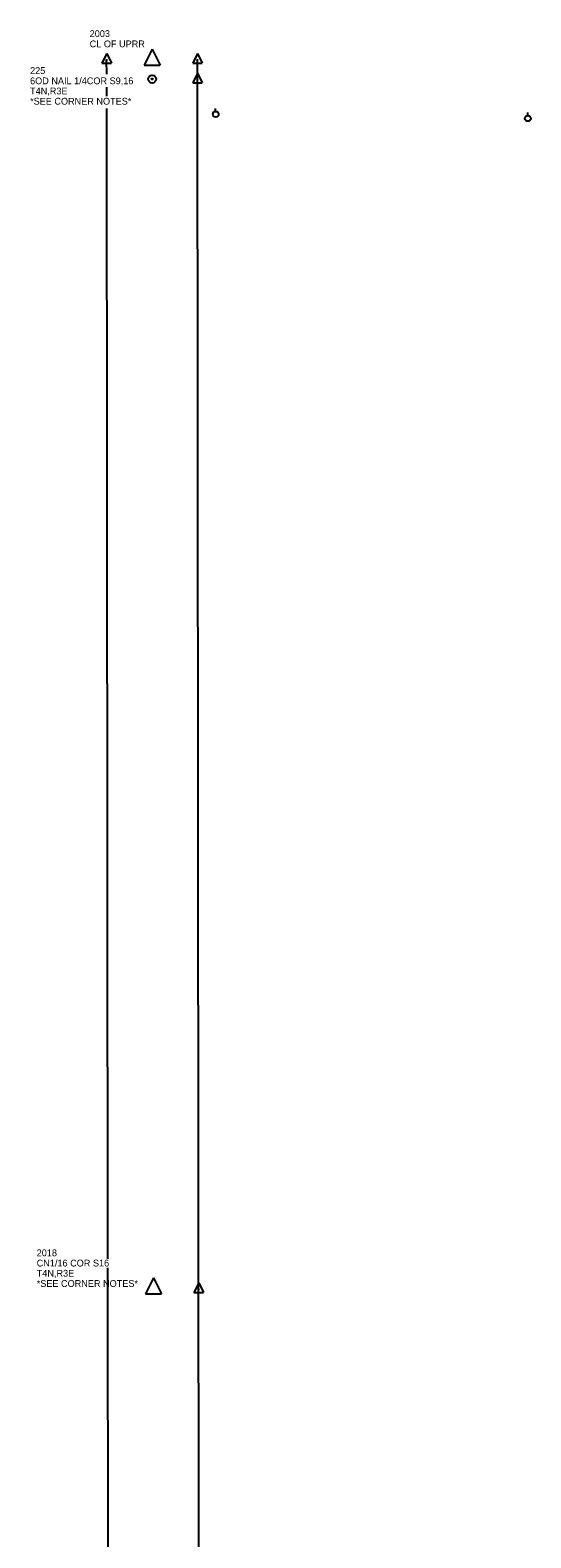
# Model space of a CAD drawing. Extents: x 1674300 to 1677920, y 225056 to 231852.
# Drawn here: x 1674554 to 1675105, y 230191 to 231852 of the extents above; entities that cross this region are included whole.
import ezdxf

# ---------------------------------------------------------------- set-up
doc = ezdxf.new("R2010")
doc.units = 0
for name, color, linetype in [('S_CAL_CORNER', 7, 'Continuous'), ('S_CAL_CORNER_ANNOT', 7, 'Continuous'), ('S_EXIST_ROW', 7, 'Continuous'), ('S_IRON_PIN', 7, 'Continuous'), ('S_IRON_PIN_ANNOT', 7, 'Continuous'), ('S_UTILITY_POLE', 7, 'Continuous')]:
    doc.layers.add(name, color=color, linetype=linetype)

msp = doc.modelspace()

# ---------------------------------------------------------------- linework, layer by layer
at = {"layer": 'S_CAL_CORNER'}
for p, q in [((1674688.7, 231831.5), (1674679.9, 231813.8)), ((1674688.7, 231831.5), (1674697.4, 231813.8)), ((1674679.9, 231813.8), (1674697.4, 231813.8)), ((1674690.1, 230477.8), (1674681.3, 230460.1)), ((1674690.1, 230477.8), (1674698.8, 230460.1)), ((1674681.3, 230460.1), (1674698.8, 230460.1))]:
    msp.add_line(p, q, dxfattribs=at)
at = {"layer": 'S_EXIST_ROW'}
for p, q in [((1674638.6, 231826.6), (1674633.3, 231816)), ((1674633.3, 231816), (1674643.8, 231816)), ((1674638.5, 231819.5), (1674638.5, 231819.5)), ((1674638.6, 231803.8), (1674638.5, 231819.5)), ((1674638.6, 231826.6), (1674643.8, 231816)), ((1674738.6, 231826.7), (1674733.3, 231816.1)), ((1674733.3, 231816.1), (1674743.8, 231816.1)), ((1674738.5, 231819.6), (1674738.5, 231819.6)), ((1674743.8, 226481.8), (1674738.5, 231819.6)), ((1674738.6, 231826.7), (1674743.8, 231816.1)), ((1674738.6, 231804.9), (1674733.3, 231794.3)), ((1674738.6, 231804.9), (1674743.8, 231794.3)), ((1674738.6, 231797.8), (1674738.6, 231797.8)), ((1674638.6, 231779.6), (1674638.6, 231789.7)), ((1674733.3, 231794.3), (1674743.8, 231794.3)), ((1674639.8, 230498.5), (1674638.6, 231766.3)), ((1674642.4, 227849.2), (1674639.8, 230488.9)), ((1674739.9, 230472.3), (1674734.6, 230461.7)), ((1674739.9, 230472.3), (1674745.1, 230461.7)), ((1674734.6, 230461.7), (1674745.1, 230461.7)), ((1674739.9, 230465.2), (1674739.9, 230465.2))]:
    msp.add_line(p, q, dxfattribs=at)
for centre, radius in [((1674638.5, 231819.5), 0.18), ((1674638.5, 231819.5), 0.09), ((1674738.5, 231819.6), 0.18), ((1674738.5, 231819.6), 0.09), ((1674738.6, 231797.8), 0.18), ((1674738.6, 231797.8), 0.09), ((1674739.9, 230465.2), 0.18), ((1674739.9, 230465.2), 0.09)]:
    msp.add_circle(centre, radius, dxfattribs=at)
at = {"layer": 'S_IRON_PIN'}
for radius in [4.36, 0.617, 0.392, 0.317, 0.218, 0.0872, 0.123]:
    msp.add_circle((1674688.7, 231798.6), radius, dxfattribs=at)
at = {"layer": 'S_UTILITY_POLE'}
for p, q in [((1674758.4, 231763), (1674758.4, 231766.2)), ((1675102.1, 231758.5), (1675102.1, 231761.6))]:
    msp.add_line(p, q, dxfattribs=at)
for centre in [(1674758.6, 231759.8), (1675102.2, 231755.3)]:
    msp.add_circle(centre, 3.19, dxfattribs=at)

# ---------------------------------------------------------------- texts
at = {"layer": 'S_CAL_CORNER_ANNOT'}
for s, p in [('2003', (1674619.9, 231844.9)), ('CL OF UPRR', (1674619.9, 231833.6)), ('2018', (1674561.6, 230501.5)), ('T4N,R3E', (1674561.6, 230479)), ('CN1/16 COR S16', (1674561.6, 230490.2)), ('*SEE CORNER NOTES*', (1674561.6, 230467.7))]:
    msp.add_text(s, height=7.5, rotation=360, dxfattribs=at).set_placement(p)
at = {"layer": 'S_IRON_PIN_ANNOT'}
for s, p in [('225', (1674554.3, 231804.2)), ('6OD NAIL 1/4COR S9,16', (1674554.3, 231792.9)), ('T4N,R3E', (1674554.3, 231781.7)), ('*SEE CORNER NOTES*', (1674554.3, 231770.4))]:
    msp.add_text(s, height=7.5, rotation=360, dxfattribs=at).set_placement(p)

doc.saveas('drawing.dxf')
